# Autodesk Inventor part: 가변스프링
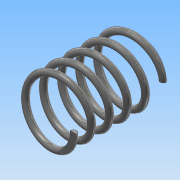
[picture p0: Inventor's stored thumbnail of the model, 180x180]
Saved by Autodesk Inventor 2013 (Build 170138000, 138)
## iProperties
Created: 2017-12
Part Number: 가변스프링
Material: 스테인리스강
Document SubType Name: Modeling
Designer: Administrator
Density: 8.08 g/cm^3
Mass: 7.07659 g
Surface Area: 17.7405 cm^2
Volume: 0.875816 cm^3
Author: Administrator
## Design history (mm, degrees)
sketch "스케치1"
  geometry: L1 (0, 0)-(9, 0); L2 (9, 0)-(9, -28.491); L3 (9, -28.491)-(0, -28.491); L4 (0, -28.491)-(0, 0); C1 r 1 at (9, 0); 1 further point
  constraints: 8 end point, 2 coincident, 2 parallel, 1 centre point, 1 horizontal, 1 perpendicular
  dimensions: "d0" = 18 diameter of L2 L4; "d2" = 28.49093 distance of L1.end L2.end (derived); "d3" = 2 diameter of C1
feature "코일1" sketch "스케치1" pitch "d4" = 10; turns "d6" = 5; dims "d5" = 28.49093 (= d2), "d7" = 0, angle "d8" = 90 deg, angle "d9" = 90 deg, "d10" = 0, "d11" = 0
sketch "스케치2"
  geometry: L1 (0, 15)-(-28.491, 15); L2 (-28.491, 15)-(-28.491, -15); L3 (-28.491, -15)-(0, -15); L4 (0, -15)-(0, 15); 4 further points
  constraints: 8 end point, 2 coincident, 2 midpoint, 2 parallel, 1 horizontal, 1 perpendicular
  dimensions: "d12" = 30 distance of L1.end L2.end
extrude "돌출1" sketch "스케치2" stored distance "d14" = 0; taper "d15" = 0 deg
node "솔리드1"
